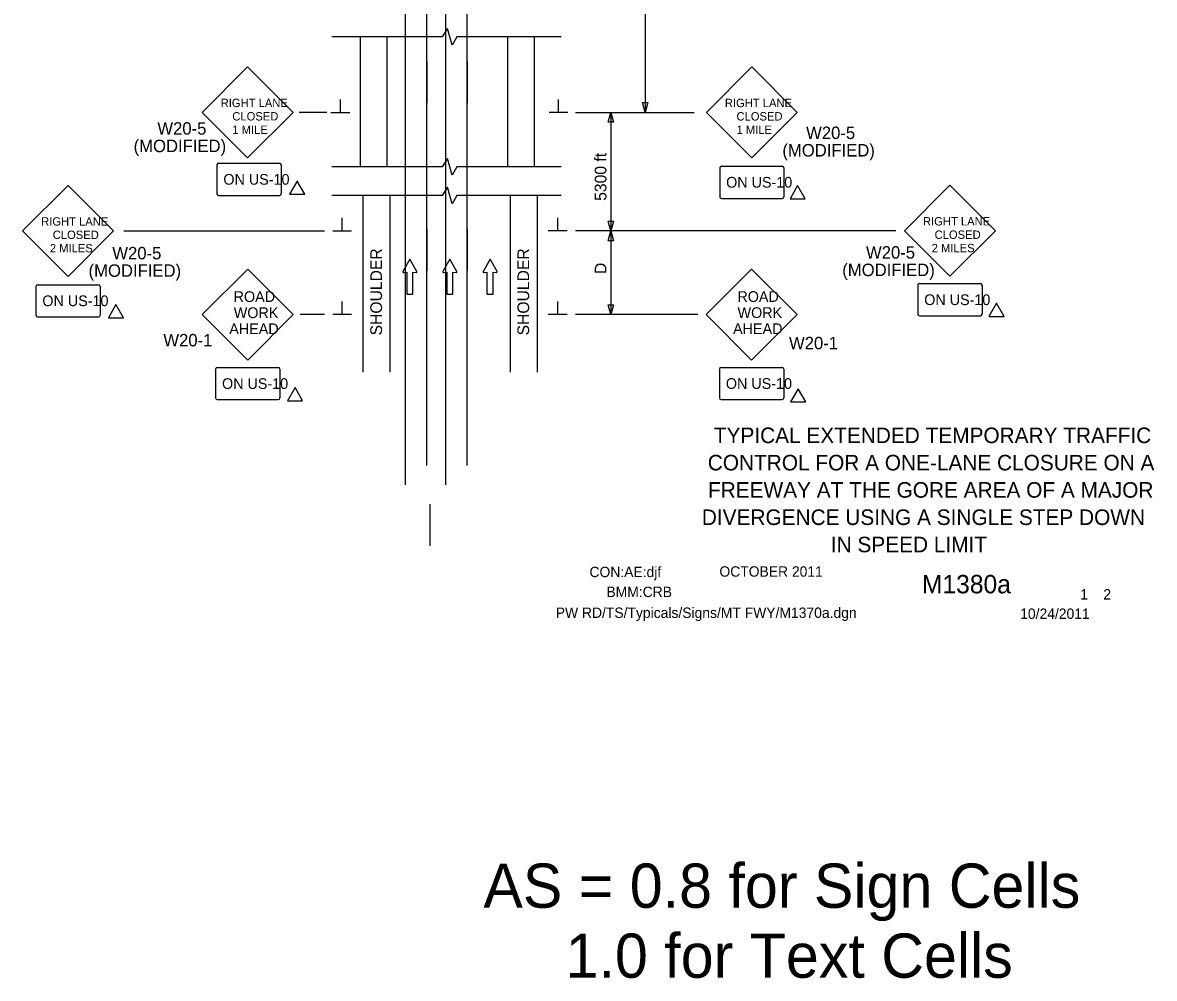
# Model space of a CAD drawing. Extents: x 16751 to 18479, y 5718 to 6974.
# Drawn here: x 16752 to 17428, y 5718 to 6289 of the extents above; entities that cross this region are included whole.
import ezdxf

# ---------------------------------------------------------------- set-up
doc = ezdxf.new("R2010")
doc.units = 0
for name, color, linetype in [('ALI_LEGAL_EX', 7, 'Continuous'), ('BORDER', 7, 'Continuous'), ('BORDER_SIGNAL_WO', 7, 'Continuous'), ('MT_SCRATCH_LEVEL_E', 7, 'Continuous'), ('PAVT_EDGE_EX', 7, 'Continuous'), ('TRAFFIC_SIGNS_PR', 7, 'Continuous'), ('TYPICAL_TEXT_DIMEN_PR', 7, 'Continuous')]:
    doc.layers.add(name, color=color, linetype=linetype)

msp = doc.modelspace()

# ---------------------------------------------------------------- linework, layer by layer
at = {"layer": 'ALI_LEGAL_EX'}
for p, q in [((16980.68, 6974.12), (16980.68, 6155.98)), ((17004.68, 6974.12), (17004.68, 6155.98)), ((16980.68, 6877.04), (16980.68, 6013.12)), ((17004.68, 6877.04), (17004.68, 6013.12)), ((16993.65, 6024.8), (16993.65, 6525.15)), ((17017.65, 6024.8), (17017.65, 6525.15))]:
    msp.add_line(p, q, dxfattribs=at)
for points in [[(16993.75, 6241.12), (16993.75, 6266.12)], [(17017.75, 6241.12), (17017.75, 6266.12)], [(16993.8, 6141.11), (16993.8, 6166.11)], [(17017.8, 6141.11), (17017.8, 6166.11)], [(16995.37, 6001.71), (16995.37, 5976.71)]]:
    msp.add_lwpolyline(points, dxfattribs=at)
at = {"layer": 'MT_SCRATCH_LEVEL_E'}
for p, q in [((16983.38, 6147.91), (16979.27, 6140.67)), ((16987.53, 6140.67), (16983.38, 6147.91)), ((17007.29, 6147.91), (17003.18, 6140.67)), ((17011.44, 6140.67), (17007.29, 6147.91)), ((17031.34, 6147.91), (17027.23, 6140.67)), ((17035.49, 6140.67), (17031.34, 6147.91)), ((16979.76, 6139.98), (16981.53, 6140.3)), ((16981.53, 6140.3), (16981.53, 6127.04)), ((16985.27, 6127.04), (16985.27, 6140.3)), ((16985.27, 6140.3), (16987.05, 6139.98)), ((17003.66, 6139.98), (17005.44, 6140.3)), ((17005.44, 6140.3), (17005.44, 6127.04)), ((17009.18, 6127.04), (17009.18, 6140.3)), ((17009.18, 6140.3), (17010.96, 6139.98)), ((17027.71, 6139.98), (17029.49, 6140.3)), ((17029.49, 6140.3), (17029.49, 6127.04)), ((17033.23, 6127.04), (17033.23, 6140.3)), ((17033.23, 6140.3), (17035.01, 6139.98)), ((16981.53, 6127.04), (16985.27, 6127.04)), ((17005.44, 6127.04), (17009.18, 6127.04)), ((17029.49, 6127.04), (17033.23, 6127.04))]:
    msp.add_line(p, q, dxfattribs=at)
for centre, start, end in [((16979.68, 6140.44), 150.42484, 279.96381), ((16987.12, 6140.44), 260.03619, 29.77312), ((17003.58, 6140.44), 150.42484, 279.96381), ((17011.03, 6140.44), 260.03619, 29.77312), ((17027.64, 6140.44), 150.42484, 279.96381), ((17035.08, 6140.44), 260.03619, 29.77312)]:
    msp.add_arc(centre, 0.463, start, end, dxfattribs=at)
at = {"layer": 'PAVT_EDGE_EX'}
for p, q in [((16953.65, 6280.88), (16953.65, 6203.23)), ((16969.65, 6280.88), (16969.65, 6203.23)), ((17041.65, 6280.88), (17041.65, 6203.23)), ((17057.65, 6280.88), (17057.65, 6203.23)), ((16955.37, 6186.1), (16955.37, 6080.42)), ((16971.37, 6186.1), (16971.37, 6080.42)), ((17043.37, 6186.1), (17043.37, 6080.42)), ((17059.37, 6186.1), (17059.37, 6080.42))]:
    msp.add_line(p, q, dxfattribs=at)
at = {"layer": 'TRAFFIC_SIGNS_PR'}
for p, q in [((16886.56, 6262.83), (16859.41, 6235.68)), ((16913.71, 6235.68), (16886.56, 6262.83)), ((17187.66, 6262.81), (17160.51, 6235.66)), ((17214.81, 6235.66), (17187.66, 6262.81)), ((16859.41, 6235.68), (16886.56, 6208.53)), ((16886.56, 6208.53), (16913.71, 6235.68)), ((17160.51, 6235.66), (17187.66, 6208.51)), ((17187.66, 6208.51), (17214.81, 6235.66)), ((16869.23, 6205.27), (16905.64, 6205.27)), ((16868.23, 6204.27), (16868.23, 6187.07)), ((16906.64, 6204.27), (16906.64, 6187.07)), ((17168.46, 6202.51), (17168.46, 6185.3)), ((17169.46, 6203.51), (17205.86, 6203.51)), ((17206.86, 6202.51), (17206.86, 6185.3)), ((16779.33, 6192.03), (16752.18, 6164.88)), ((16806.48, 6164.88), (16779.33, 6192.03)), ((17305.97, 6192.12), (17278.82, 6164.97)), ((17333.12, 6164.97), (17305.97, 6192.12)), ((16869.23, 6186.07), (16905.64, 6186.07)), ((17169.46, 6184.3), (17205.86, 6184.3)), ((16752.18, 6164.88), (16779.33, 6137.73)), ((16779.33, 6137.73), (16806.48, 6164.88)), ((17278.82, 6164.97), (17305.97, 6137.82)), ((17305.97, 6137.82), (17333.12, 6164.97)), ((16886.63, 6142.03), (16859.47, 6114.88)), ((16913.78, 6114.88), (16886.63, 6142.03)), ((17187.49, 6142.07), (17160.34, 6114.91)), ((17214.65, 6114.91), (17187.49, 6142.07)), ((16760.12, 6131.73), (16760.12, 6114.52)), ((16761.12, 6132.73), (16797.53, 6132.73)), ((16798.53, 6131.73), (16798.53, 6114.52)), ((17286.77, 6132.37), (17286.77, 6115.17)), ((17287.77, 6133.37), (17324.18, 6133.37)), ((17325.18, 6132.37), (17325.18, 6115.17)), ((16761.12, 6113.52), (16797.53, 6113.52)), ((16859.47, 6114.88), (16886.63, 6087.72)), ((16886.63, 6087.72), (16913.78, 6114.88)), ((17160.34, 6114.91), (17187.49, 6087.76)), ((17187.49, 6087.76), (17214.65, 6114.91)), ((17287.77, 6114.17), (17324.18, 6114.17)), ((16868.42, 6083.28), (16904.83, 6083.28)), ((17169.29, 6083.31), (17205.7, 6083.31)), ((16867.42, 6082.28), (16867.42, 6065.07)), ((16905.83, 6082.28), (16905.83, 6065.07)), ((17168.29, 6082.31), (17168.29, 6065.11)), ((17206.7, 6082.31), (17206.7, 6065.11)), ((16868.42, 6064.07), (16904.83, 6064.07)), ((17169.29, 6064.11), (17205.7, 6064.11))]:
    msp.add_line(p, q, dxfattribs=at)
for centre, start, end in [((16869.23, 6204.27), 90, 180), ((16905.64, 6204.27), 0, 90), ((17169.46, 6202.51), 90, 180), ((17205.86, 6202.51), 0, 90), ((16869.23, 6187.07), 180, 270), ((16905.64, 6187.07), 270, 0), ((17169.46, 6185.31), 180, 270), ((17205.86, 6185.31), 270, 0), ((16761.12, 6131.73), 90, 180), ((16797.53, 6131.73), 0, 90), ((17287.77, 6132.37), 90, 180), ((17324.18, 6132.37), 0, 90), ((16761.12, 6114.52), 180, 270), ((16797.53, 6114.52), 270, 0), ((17287.77, 6115.17), 180, 270), ((17324.18, 6115.17), 270, 0), ((16868.42, 6082.28), 90, 180), ((16904.83, 6082.28), 0, 90), ((17169.29, 6082.31), 90, 180), ((17205.7, 6082.31), 0, 90), ((16868.42, 6065.07), 180, 270), ((16904.83, 6065.07), 270, 0), ((17169.29, 6065.11), 180, 270), ((17205.7, 6065.11), 270, 0)]:
    msp.add_arc(centre, 1, start, end, dxfattribs=at)
at = {"layer": 'TYPICAL_TEXT_DIMEN_PR'}
for p, q in [((17124.01, 6619.33), (17124.01, 6235.65)), ((17005.97, 6285.68), (17002.72, 6280.88)), ((17008.71, 6275.74), (17005.97, 6285.68)), ((17002.72, 6280.88), (16936.78, 6280.88)), ((17011.46, 6280.88), (17008.71, 6275.74)), ((17073.79, 6280.88), (17011.46, 6280.88)), ((16941.96, 6235.65), (16941.96, 6243.44)), ((17072.21, 6235.65), (17072.21, 6243.44)), ((17124.01, 6235.65), (17122.44, 6241.52)), ((17122.44, 6241.52), (17124.01, 6241.52)), ((17124.01, 6241.52), (17125.58, 6241.52)), ((17125.58, 6241.52), (17124.01, 6235.65)), ((16933.91, 6235.65), (16917.23, 6235.65)), ((16936.33, 6235.65), (16947.58, 6235.65)), ((17077.83, 6235.65), (17066.58, 6235.65)), ((17082.37, 6235.65), (17153.28, 6235.65)), ((17101.8, 6229.79), (17103.37, 6235.65)), ((17103.37, 6235.65), (17103.37, 6164.88)), ((17103.37, 6235.65), (17104.94, 6229.79)), ((17103.37, 6229.79), (17101.8, 6229.79)), ((17104.94, 6229.79), (17103.37, 6229.79)), ((17005.97, 6208.03), (17002.72, 6203.23)), ((17008.71, 6198.1), (17005.97, 6208.03)), ((17002.72, 6203.23), (16936.78, 6203.23)), ((17011.46, 6203.23), (17008.71, 6198.1)), ((17073.79, 6203.23), (17011.46, 6203.23)), ((17002.72, 6186.1), (16936.78, 6186.1)), ((17005.97, 6190.9), (17002.72, 6186.1)), ((17008.71, 6180.96), (17005.97, 6190.9)), ((17011.46, 6186.1), (17008.71, 6180.96)), ((17073.79, 6186.1), (17011.46, 6186.1)), ((16942.99, 6164.88), (16942.99, 6172.66)), ((17071.74, 6164.88), (17071.74, 6172.66)), ((17103.37, 6164.88), (17101.8, 6170.74)), ((17101.8, 6170.74), (17103.37, 6170.74)), ((17103.37, 6170.74), (17104.94, 6170.74)), ((17104.94, 6170.74), (17103.37, 6164.88)), ((16812.54, 6164.88), (16932.37, 6164.88)), ((16937.37, 6164.88), (16948.62, 6164.88)), ((17077.37, 6164.88), (17066.12, 6164.88)), ((17273.56, 6164.88), (17082.37, 6164.88)), ((17101.8, 6159.01), (17103.37, 6164.88)), ((17103.37, 6164.88), (17103.37, 6114.88)), ((17103.37, 6164.88), (17104.94, 6159.01)), ((17103.37, 6159.01), (17101.8, 6159.01)), ((17104.94, 6159.01), (17103.37, 6159.01)), ((16942.99, 6114.88), (16942.99, 6122.66)), ((17071.74, 6114.88), (17071.74, 6122.66)), ((17103.37, 6114.88), (17101.8, 6120.74)), ((17101.8, 6120.74), (17103.37, 6120.74)), ((17103.37, 6120.74), (17104.94, 6120.74)), ((17104.94, 6120.74), (17103.37, 6114.88)), ((16932.37, 6114.88), (16917.97, 6114.88)), ((16948.62, 6114.88), (16937.37, 6114.88)), ((17077.37, 6114.88), (17066.12, 6114.88)), ((17155.4, 6114.88), (17082.37, 6114.88))]:
    msp.add_line(p, q, dxfattribs=at)
for points in [[(16916.12, 6194.56), (16911.59, 6186.72), (16920.65, 6186.72)], [(17215.01, 6191.95), (17210.49, 6184.11), (17219.54, 6184.11)], [(16807.93, 6120.86), (16803.41, 6113.03), (16812.46, 6113.03)], [(17333.77, 6121.63), (17329.25, 6113.8), (17338.3, 6113.8)], [(16914.88, 6071.28), (16910.35, 6063.44), (16919.41, 6063.44)], [(17215.29, 6070.61), (17210.77, 6062.78), (17219.82, 6062.78)]]:
    msp.add_lwpolyline(points, close=True, dxfattribs=at)

# ---------------------------------------------------------------- texts
at = {"layer": 'BORDER'}
for s, p in [('TYPICAL EXTENDED TEMPORARY TRAFFIC', (17164.96, 6038.11)), ('CONTROL FOR A ONE-LANE CLOSURE ON A', (17161.34, 6021.81)), ('FREEWAY AT THE GORE AREA OF A MAJOR', (17161.47, 6005.51)), (' DIVERGENCE USING A SINGLE STEP DOWN ', (17154.34, 5989.2)), ('IN SPEED LIMIT', (17234.84, 5972.9))]:
    msp.add_text(s, height=9.3, dxfattribs=at).set_placement(p)
at = {"layer": 'BORDER_SIGNAL_WO'}
for s, height, p in [('CON:AE:djf  ', 6.2, (17090.69, 5958.06)), ('    OCTOBER 2011    ', 6.2, (17159.08, 5958.34)), ('    M1380a   ', 11, (17272.86, 5948.38)), ('BMM:CRB   ', 6.2, (17100.81, 5946.17)), (' 1    2 ', 6.2, (17381.45, 5944.7)), ('PW RD/TS/Typicals/Signs/MT FWY/M1370a.dgn      ', 6.2, (17070.55, 5933.71)), ('10/24/2011    ', 6.2, (17347.93, 5933.13)), ('AS = 0.8 for Sign Cells', 26.4241, (17027.34, 5760.56)), ('     1.0 for Text Cells', 26.4241, (17027.34, 5718.77))]:
    msp.add_text(s, height=height, dxfattribs=at).set_placement(p)
at = {"layer": 'TRAFFIC_SIGNS_PR'}
for s, height, p in [('RIGHT LANE', 4.999, (16870.45, 6238.83)), ('RIGHT LANE', 4.999, (17171.55, 6238.81)), ('CLOSED', 4.999, (16877.4, 6230.83)), ('CLOSED', 4.999, (17178.5, 6230.81)), ('W20-5', 7.439, (16832.63, 6222.36)), ('1 MILE', 4.999, (16877.4, 6222.83)), ('1 MILE', 4.999, (17178.5, 6222.82)), ('W20-5', 7.439, (17220.06, 6219.75)), ('(MODIFIED)', 7.439, (16818.45, 6211.92)), ('(MODIFIED)', 7.439, (17205.88, 6209.31)), ('ON US-10', 6.401, (16872.07, 6192.47)), ('ON US-10', 6.401, (17172.3, 6190.71)), ('RIGHT LANE', 4.999, (16763.21, 6168.03)), ('RIGHT LANE', 4.999, (17289.85, 6168.12)), ('CLOSED', 4.999, (16770.16, 6160.03)), ('CLOSED', 4.999, (17296.81, 6160.12)), ('2 MILES', 4.999, (17295.06, 6152.12)), ('2 MILES', 4.999, (16768.41, 6152.03)), ('W20-5', 7.439, (16805.73, 6147.88)), ('W20-5', 7.439, (17255.83, 6148.31)), ('(MODIFIED)', 7.439, (16791.55, 6137.44)), ('(MODIFIED)', 7.439, (17241.65, 6137.87)), ('ON US-10', 6.401, (16763.96, 6119.93)), ('ROAD', 6.401, (16878.17, 6122.41)), ('ROAD', 6.401, (17179.04, 6122.45)), ('ON US-10', 6.401, (17290.61, 6120.57)), ('WORK', 6.401, (16878.28, 6112.81)), ('WORK', 6.401, (17179.14, 6112.85)), ('W20-1', 7.441, (16836.21, 6095.88)), ('AHEAD', 6.401, (16875.59, 6103.21)), ('AHEAD', 6.401, (17176.45, 6103.25)), ('W20-1', 7.441, (17209.84, 6094.15)), ('ON US-10', 6.401, (16871.26, 6070.47)), ('ON US-10', 6.401, (17172.13, 6070.51))]:
    msp.add_text(s, height=height, dxfattribs=at).set_placement(p)
at = {"layer": 'TYPICAL_TEXT_DIMEN_PR'}
for s, p in [('5300 ft', (17100.81, 6182.83)), ('SHOULDER', (16966.81, 6102.45)), ('SHOULDER', (17054.67, 6102.45)), ('D', (17100.81, 6139.1))]:
    msp.add_text(s, height=7, rotation=90, dxfattribs=at).set_placement(p)

doc.saveas('drawing.dxf')
